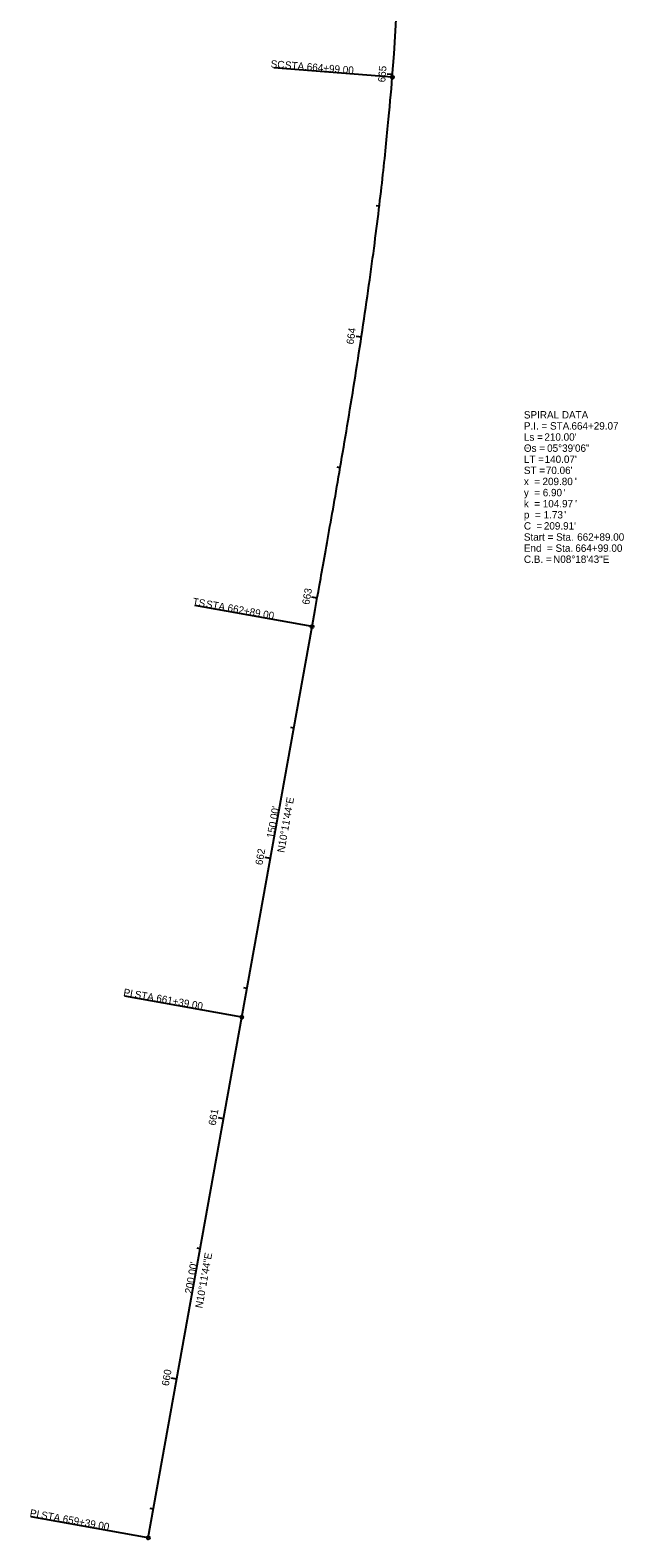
# Model space of a CAD drawing. Extents: x 171681 to 172332, y 456784 to 458794.
# Drawn here: x 172108 to 172332, y 457661 to 458231 of the extents above; entities that cross this region are included whole.
import ezdxf

# ---------------------------------------------------------------- set-up
doc = ezdxf.new("R2010")
doc.units = 0
for name, color, linetype in [('GE_X_Alignment', 7, 'Continuous'), ('GE_X_Alignment_100_Bearings', 7, 'Continuous'), ('GE_X_Alignment_100_Cardinal_Points', 7, 'Continuous'), ('GE_X_Alignment_100_Curve_Data', 7, 'Continuous'), ('GE_X_Alignment_100_Distances', 7, 'Continuous'), ('GE_X_Alignment_100_Stations', 7, 'Continuous')]:
    doc.layers.add(name, color=color, linetype=linetype)

msp = doc.modelspace()

# ---------------------------------------------------------------- linework, layer by layer
at = {"layer": 'GE_X_Alignment'}
for p, q in [((172187.78, 457857.62), (172214.34, 458005.25)), ((172187.78, 457857.62), (172214.34, 458005.25)), ((172187.78, 457857.62), (172214.34, 458005.25)), ((172152.38, 457660.78), (172187.78, 457857.62)), ((172152.38, 457660.78), (172187.78, 457857.62)), ((172152.38, 457660.78), (172187.78, 457857.62))]:
    msp.add_line(p, q, dxfattribs=at)
msp.add_arc((171183.53, 458297.29), 1064.5, 355.45598, 25.63893, dxfattribs=at)
msp.add_arc((171183.53, 458297.29), 1064.5, 355.45598, 25.63893, dxfattribs=at)
msp.add_open_spline([(172214.34, 458005.25), (172215.37, 458010.99), (172217.43, 458022.47), (172221.53, 458045.44), (172226.54, 458074.18), (172232.17, 458108.72), (172237.23, 458143.36), (172240.81, 458172.3), (172243.2, 458195.52), (172244.22, 458207.14), (172244.68, 458212.95)], degree=3, dxfattribs=at)
msp.add_open_spline([(172214.34, 458005.25), (172215.37, 458010.99), (172217.43, 458022.47), (172221.53, 458045.44), (172226.54, 458074.18), (172232.17, 458108.72), (172237.23, 458143.36), (172240.81, 458172.3), (172243.2, 458195.52), (172244.22, 458207.14), (172244.68, 458212.95)], degree=3, dxfattribs=at)
at = {"layer": 'GE_X_Alignment_100_Cardinal_Points'}
for p, q in [((172244.68, 458212.95), (172199.82, 458216.52)), ((172214.34, 458005.25), (172170.05, 458013.21)), ((172187.78, 457857.62), (172143.49, 457865.58)), ((172152.38, 457660.78), (172108.09, 457668.74))]:
    msp.add_line(p, q, dxfattribs=at)
for centre in [(172244.68, 458212.95), (172214.34, 458005.25), (172187.78, 457857.62), (172152.38, 457660.78)]:
    msp.add_circle(centre, 0.6, dxfattribs=at)
at = {"layer": 'GE_X_Alignment_100_Stations'}
for p, q in [((172244.76, 458213.95), (172242.77, 458214.11)), ((172239.76, 458164.21), (172238.57, 458164.35)), ((172232.98, 458114.67), (172231, 458114.97)), ((172224.97, 458065.32), (172223.78, 458065.52)), ((172216.28, 458016.08), (172214.31, 458016.43)), ((172207.43, 457966.87), (172206.25, 457967.08)), ((172198.58, 457917.66), (172196.61, 457918.01)), ((172189.73, 457868.45), (172188.55, 457868.66)), ((172180.88, 457819.24), (172178.91, 457819.59)), ((172172.03, 457770.03), (172170.85, 457770.24)), ((172163.18, 457720.82), (172161.21, 457721.17)), ((172154.33, 457671.61), (172153.15, 457671.82))]:
    msp.add_line(p, q, dxfattribs=at)

# ---------------------------------------------------------------- texts
at = {"layer": 'GE_X_Alignment_100_Bearings'}
for p in [(172203.82, 457919.64), (172172.84, 457747.41)]:
    msp.add_text('N10°11\'44"E', height=2.8, rotation=79.8044, dxfattribs=at).set_placement(p)
at = {"layer": 'GE_X_Alignment_100_Cardinal_Points'}
for s, rotation, p in [('SC', 355.456, (172198.61, 458216.65)), (' STA. ', 355.456, (172202.96, 458216.31)), ('664+99.00', 355.456, (172212.25, 458215.57)), ('TS', 349.8044, (172168.98, 458013.44)), (' STA. ', 349.8044, (172173.02, 458012.72)), ('662+89.00', 349.8044, (172182.2, 458011.07)), ('PI', 349.8044, (172142.82, 457865.74)), (' STA. ', 349.8044, (172146.08, 457865.15)), ('661+39.00', 349.8044, (172155.26, 457863.5)), ('PI', 349.8044, (172107.42, 457668.9)), (' STA. ', 349.8044, (172110.68, 457668.31)), ('659+39.00', 349.8044, (172119.86, 457666.66))]:
    msp.add_text(s, height=2.8, rotation=rotation, dxfattribs=at).set_placement(p)
at = {"layer": 'GE_X_Alignment_100_Curve_Data'}
for s, p in [('SPIRAL DATA', (172294.45, 458083.94)), ('P.I. = STA. ', (172294.45, 458079.74)), ('Ls = ', (172294.45, 458075.54)), ("210.00'", (172302.2, 458075.54)), ('664+29.07', (172312.44, 458079.74)), ('Θs = ', (172294.45, 458071.34)), ('05°39\'06"', (172303.24, 458071.34)), ('ST = ', (172294.45, 458062.94)), ('LT = ', (172294.45, 458067.14)), ("140.07'", (172302.3, 458067.14)), ("70.06'", (172302.75, 458062.94)), ('x  = ', (172294.45, 458058.74)), ('209.80', (172301.49, 458058.74)), ("'", (172313.74, 458058.74)), ('y  = ', (172294.45, 458054.54)), ('6.90', (172301.59, 458054.54)), ("'", (172309.37, 458054.54)), ('k  = ', (172294.45, 458050.34)), ('104.97', (172301.59, 458050.34)), ('1.73', (172301.93, 458046.14)), ("'", (172309.72, 458046.14)), ("'", (172313.84, 458050.34)), ('C  = ', (172294.45, 458041.94)), ('p  = ', (172294.45, 458046.14)), ("209.91'", (172302, 458041.94)), ('Start = Sta. ', (172294.45, 458037.74)), ('662+89.00', (172314.6, 458037.74)), ('C.B. = ', (172294.45, 458029.34)), ('End  = Sta. ', (172294.45, 458033.54)), ('N08°18\'43"E', (172305.52, 458029.34)), ('664+99.00', (172313.91, 458033.54))]:
    msp.add_text(s, height=2.8, dxfattribs=at).set_placement(p)
at = {"layer": 'GE_X_Alignment_100_Distances'}
for s, p in [("150.00'", (172199.88, 457925.1)), ("200.00'", (172168.91, 457752.87))]:
    msp.add_text(s, height=2.8, rotation=79.8044, dxfattribs=at).set_placement(p)
at = {"layer": 'GE_X_Alignment_100_Stations'}
for s, rotation, p in [('665', 85.51, (172242.02, 458210.95)), ('664', 81.3835, (172230.02, 458111.8)), ('663', 79.82, (172213.26, 458013.37)), ('662', 79.8044, (172195.55, 457914.94)), ('661', 79.8044, (172177.85, 457816.51)), ('660', 79.8044, (172160.14, 457718.04))]:
    msp.add_text(s, height=2.8, rotation=rotation, dxfattribs=at).set_placement(p)

doc.saveas('drawing.dxf')
